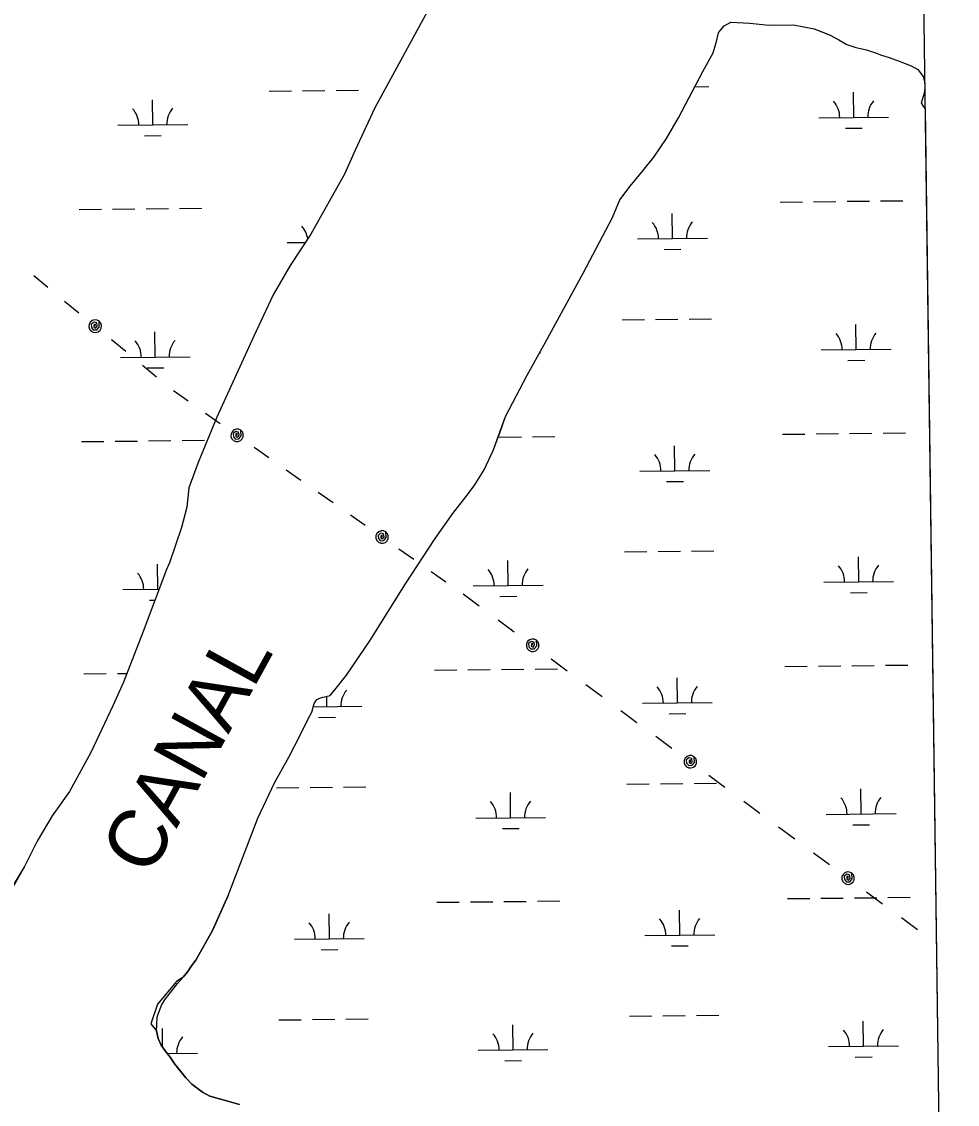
# Model space of a CAD drawing. Extents: x 3734862 to 3772949, y 391520 to 417239.
# Drawn here: x 3769504 to 3770844, y 399269 to 400820 of the extents above; entities that cross this region are included whole.
import ezdxf

# ---------------------------------------------------------------- set-up
doc = ezdxf.new("R2010")
doc.units = 0
for name, color, linetype in [('V-GRID-FRAM', 7, 'Continuous'), ('V-RIVR-IDEN', 7, 'Continuous'), ('V-TOPO-SHOR', 7, 'Continuous'), ('V-UTIL-LINE', 7, 'Continuous'), ('V-WETL-SWMP', 7, 'Continuous')]:
    doc.layers.add(name, color=color, linetype=linetype)

msp = doc.modelspace()

# ---------------------------------------------------------------- linework, layer by layer
at = {"layer": 'V-GRID-FRAM'}
msp.add_lwpolyline([(3738832.3, 415033.8), (3770599.2, 415447.4), (3770843.8, 397266.6), (3739061.1, 396852.8), (3738832.3, 415033.8)], dxfattribs=at)
at = {"layer": 'V-TOPO-SHOR'}
for p, q in [((3769725.6, 399444.6), (3769698.5, 399412.3)), ((3769698.5, 399412.3), (3769688.7, 399384))]:
    msp.add_line(p, q, dxfattribs=at)
for points in [[(3770096, 400855.5), (3770009.8, 400696.7), (3769981.4, 400635.8), (3769966.3, 400601.7), (3769917.9, 400515.4), (3769888.6, 400470.9), (3769864, 400428.4), (3769836.3, 400369.6), (3769783.6, 400253.4), (3769756.6, 400188.5), (3769743.5, 400152.3), (3769740.5, 400124.4), (3769732.8, 400095.1), (3769715.8, 400044.6), (3769711.2, 400035), (3769677.7, 399946.2), (3769649.5, 399873.8), (3769634.4, 399839.7), (3769602.7, 399772.7), (3769572.2, 399717.2), (3769547.5, 399682.2), (3769526.3, 399645.9), (3769507.8, 399609.7), (3769479.7, 399559.2)], [(3769799.4, 399568.1), (3769842, 399678.7), (3769865.8, 399729.3), (3769886.4, 399766.3), (3769903.6, 399799.8), (3769914.1, 399821), (3769919.4, 399830.6), (3769922.7, 399842.9), (3769926.7, 399849), (3769933.4, 399851.8), (3769945.6, 399854.7), (3769954.3, 399865), (3769969, 399883.6), (3770002.3, 399932.9), (3770053.5, 400014.5), (3770096.1, 400079.6), (3770121.4, 400115.3), (3770140.1, 400139.3), (3770152.1, 400155.1), (3770166, 400177.7), (3770179.2, 400205.7), (3770188.4, 400231), (3770196.9, 400254.2), (3770228, 400313.7), (3770253.9, 400361), (3770308.2, 400459.5), (3770349.9, 400539.6), (3770360.5, 400564.9), (3770375.1, 400584.1), (3770393.2, 400606.1), (3770409.2, 400626), (3770427.2, 400652.7), (3770444.4, 400682.2), (3770460.3, 400712.3), (3770479.5, 400748.6), (3770494.1, 400775.3), (3770498.7, 400791.6), (3770501.9, 400803.9), (3770504.5, 400808), (3770509.9, 400814.2), (3770519.3, 400819.1), (3770546.5, 400818.1), (3770573.7, 400815.1), (3770609.1, 400815.6), (3770639, 400809.9), (3770648.6, 400805.9), (3770661.6, 400800.7), (3770673.9, 400794), (3770685.5, 400787.4), (3770698.5, 400782.8), (3770713.5, 400779.6), (3770725.1, 400775.7), (3770735.3, 400771.8), (3770746.2, 400768.5), (3770760.6, 400763.3), (3770777.7, 400756.7), (3770787.2, 400751.4), (3770794.9, 400741.3), (3770797.2, 400732.1)], [(3770797.3, 400725.1), (3770796.5, 400717.6), (3770796.5, 400716.9), (3770792, 400703.9), (3770795.4, 400697.9), (3770797.7, 400695.1)], [(3769799.4, 399568.1), (3769777.2, 399517.9), (3769753.5, 399475.4), (3769747.3, 399467.4), (3769741.9, 399459), (3769735.3, 399451), (3769725.6, 399444.6)], [(3769688.7, 399384), (3769697.2, 399374), (3769699.4, 399363.2), (3769703.6, 399353.6), (3769709.3, 399345.5), (3769716.6, 399336.2), (3769723.4, 399326.2), (3769731.8, 399315.8), (3769739, 399306.9), (3769747.8, 399297.6), (3769762.7, 399286), (3769773.4, 399280.6), (3769788.4, 399276.3), (3769802.6, 399272.3), (3769816, 399268.8)]]:
    msp.add_lwpolyline(points, dxfattribs=at)
at = {"layer": 'V-UTIL-LINE'}
for points in [[(3769521.1, 400456.2), (3769541.5, 400439.4)], [(3769565.4, 400419.7), (3769585.8, 400402.9)], [(3769609.1, 400383.7), (3769609.4, 400386.6), (3769607.4, 400385.4), (3769607.2, 400382.7), (3769609.7, 400381.1), (3769611.9, 400383.6), (3769611.6, 400388.3), (3769607.5, 400389.4), (3769603.5, 400386.6), (3769603.7, 400382), (3769606.5, 400378.5), (3769611.3, 400378.5), (3769615, 400382.5), (3769614.9, 400390.7), (3769611.8, 400392.3), (3769608.3, 400392.7), (3769604.9, 400391.7), (3769602.2, 400389.4), (3769600.5, 400386.3), (3769600.2, 400382.8), (3769601.2, 400379.5), (3769603.4, 400376.8), (3769606.5, 400375.1), (3769610, 400374.8), (3769613.4, 400375.8), (3769616.1, 400378), (3769617.8, 400381.1), (3769618.1, 400384.6), (3769617.1, 400387.9), (3769614.9, 400390.7)], [(3769632.5, 400364.5), (3769652.9, 400347.7)], [(3769676.8, 400328), (3769697.2, 400311.2)], [(3769721.1, 400291.5), (3769742.2, 400276.7)], [(3769767.1, 400259.2), (3769788.2, 400244.4)], [(3769812.5, 400227.4), (3769812.5, 400230.2), (3769810.6, 400228.9), (3769810.6, 400226.2), (3769813.2, 400224.8), (3769815.3, 400227.4), (3769814.6, 400232.1), (3769810.4, 400232.9), (3769806.6, 400229.8), (3769807.2, 400225.2), (3769810.2, 400221.9), (3769815, 400222.3), (3769818.4, 400226.6), (3769817.6, 400234.7), (3769814.4, 400236.1), (3769810.9, 400236.2), (3769807.6, 400235), (3769805.1, 400232.5), (3769803.7, 400229.3), (3769803.6, 400225.8), (3769804.9, 400222.5), (3769807.3, 400220), (3769810.5, 400218.6), (3769814, 400218.5), (3769817.3, 400219.8), (3769819.8, 400222.2), (3769821.2, 400225.4), (3769821.3, 400228.9), (3769820.1, 400232.2), (3769817.6, 400234.7)], [(3769836.7, 400210.3), (3769857.8, 400195.5)], [(3769882.7, 400178), (3769903.8, 400163.2)], [(3769928.7, 400145.8), (3769949.8, 400130.9)], [(3769974.6, 400113.5), (3769995.8, 400098.6)], [(3770020, 400081.6), (3770020, 400084.5), (3770018.1, 400083.2), (3770018.2, 400080.4), (3770020.7, 400079), (3770022.8, 400081.7), (3770022.1, 400086.3), (3770017.9, 400087.1), (3770014.2, 400084), (3770014.7, 400079.5), (3770017.7, 400076.2), (3770022.6, 400076.5), (3770026, 400080.8), (3770025.2, 400089), (3770022, 400090.4), (3770018.5, 400090.5), (3770015.2, 400089.2), (3770012.6, 400086.8), (3770011.2, 400083.6), (3770011.1, 400080), (3770012.4, 400076.8), (3770014.8, 400074.2), (3770018, 400072.8), (3770021.6, 400072.7), (3770024.8, 400074), (3770027.4, 400076.4), (3770028.8, 400079.6), (3770028.9, 400083.1), (3770027.6, 400086.4), (3770025.2, 400089)], [(3770044.2, 400064.6), (3770065.4, 400049.7)], [(3770090.2, 400032.3), (3770111.4, 400017.4)], [(3770136.2, 400000), (3770159.2, 399983)], [(3770186.2, 399963), (3770209.2, 399946)], [(3770235.6, 399926.5), (3770235.7, 399929.4), (3770233.8, 399928.1), (3770233.7, 399925.4), (3770236.3, 399923.9), (3770238.4, 399926.6), (3770237.8, 399931.2), (3770233.7, 399932.1), (3770229.8, 399929.1), (3770230.3, 399924.5), (3770233.2, 399921.2), (3770238, 399921.4), (3770241.6, 399925.7), (3770241, 399933.8), (3770237.8, 399935.3), (3770234.3, 399935.4), (3770231, 399934.3), (3770228.4, 399931.9), (3770226.9, 399928.7), (3770226.7, 399925.2), (3770227.9, 399921.9), (3770230.3, 399919.3), (3770233.4, 399917.8), (3770236.9, 399917.6), (3770240.3, 399918.8), (3770242.9, 399921.2), (3770244.3, 399924.4), (3770244.5, 399927.9), (3770243.3, 399931.2), (3770241, 399933.8)], [(3770262, 399907.1), (3770285, 399890.1)], [(3770312, 399870.1), (3770335, 399853.1)], [(3770362.1, 399833.1), (3770385, 399816.1)], [(3770412.1, 399796.1), (3770435.1, 399779.2)], [(3770461.5, 399759.7), (3770461.5, 399762.6), (3770459.6, 399761.3), (3770459.6, 399758.5), (3770462.1, 399757.1), (3770464.3, 399759.7), (3770463.7, 399764.3), (3770459.5, 399765.2), (3770455.7, 399762.2), (3770456.1, 399757.7), (3770459.1, 399754.3), (3770463.9, 399754.6), (3770467.4, 399758.8), (3770466.8, 399766.9), (3770463.6, 399768.4), (3770460.1, 399768.6), (3770456.8, 399767.4), (3770454.2, 399765), (3770452.7, 399761.8), (3770452.6, 399758.3), (3770453.7, 399755), (3770456.1, 399752.4), (3770459.3, 399750.9), (3770462.8, 399750.8), (3770466.1, 399752), (3770468.7, 399754.3), (3770470.2, 399757.5), (3770470.4, 399761), (3770469.2, 399764.3), (3770466.8, 399766.9)], [(3770487.8, 399740.2), (3770510.8, 399723.2)], [(3770537.9, 399703.2), (3770560.9, 399686.2)], [(3770587.9, 399666.2), (3770610.9, 399649.3)], [(3770637.9, 399629.3), (3770660.9, 399612.3)], [(3770687.3, 399592.8), (3770687.4, 399595.7), (3770685.4, 399594.4), (3770685.4, 399591.7), (3770688, 399590.2), (3770690.1, 399592.8), (3770689.5, 399597.5), (3770685.4, 399598.4), (3770681.5, 399595.4), (3770682, 399590.8), (3770684.9, 399587.4), (3770689.7, 399587.7), (3770693.3, 399591.9), (3770692.7, 399600), (3770689.5, 399601.5), (3770686, 399601.7), (3770682.7, 399600.5), (3770680.1, 399598.2), (3770678.6, 399595), (3770678.4, 399591.5), (3770679.6, 399588.2), (3770682, 399585.6), (3770685.1, 399584.1), (3770688.6, 399583.9), (3770691.9, 399585.1), (3770694.5, 399587.5), (3770696, 399590.6), (3770696.2, 399594.1), (3770695, 399597.4), (3770692.7, 399600)], [(3770713.7, 399573.3), (3770736.7, 399556.3)], [(3770763.7, 399536.4), (3770786.7, 399519.4)]]:
    msp.add_lwpolyline(points, dxfattribs=at)
at = {"layer": 'V-WETL-SWMP'}
for p, q in [((3770504.5, 400808), (3770509.9, 400814.2)), ((3770509.9, 400814.2), (3770519.3, 400819.1)), ((3770519.3, 400819.1), (3770546.5, 400818.1)), ((3770546.5, 400818.1), (3770573.7, 400815.1)), ((3770573.7, 400815.1), (3770609.1, 400815.6)), ((3770609.1, 400815.6), (3770639, 400809.9)), ((3770498.7, 400791.6), (3770501.9, 400803.9)), ((3770501.9, 400803.9), (3770504.5, 400808)), ((3770639, 400809.9), (3770661.6, 400800.7)), ((3770661.6, 400800.7), (3770673.9, 400794)), ((3770494.1, 400775.3), (3770498.7, 400791.6)), ((3770673.9, 400794), (3770685.5, 400787.4)), ((3770685.5, 400787.4), (3770698.5, 400782.8)), ((3770698.5, 400782.8), (3770713.5, 400779.6)), ((3770479.5, 400748.6), (3770494.1, 400775.3)), ((3770713.5, 400779.6), (3770725.1, 400775.7)), ((3770725.1, 400775.7), (3770735.3, 400771.8)), ((3770735.3, 400771.8), (3770746.2, 400768.5)), ((3770746.2, 400768.5), (3770760.6, 400763.3)), ((3770760.6, 400763.3), (3770777.7, 400756.7)), ((3770777.7, 400756.7), (3770787.2, 400751.4)), ((3770787.2, 400751.4), (3770794.9, 400741.3)), ((3770444.4, 400682.2), (3770479.5, 400748.6)), ((3770794.9, 400741.3), (3770797.2, 400732.1)), ((3769858.2, 400720.3), (3769890.2, 400720.7)), ((3769906.2, 400720.9), (3769938.2, 400721.2)), ((3769954.2, 400721.4), (3769986.2, 400721.7)), ((3770468, 400726.8), (3770488.1, 400727)), ((3770797.3, 400725.1), (3770796.5, 400717.6)), ((3770797.2, 400732.1), (3770797.3, 400725.1)), ((3769691.7, 400672.2), (3769691.3, 400708.2)), ((3770695.4, 400682.8), (3770695.1, 400718.8)), ((3770796.5, 400716.9), (3770792, 400703.9)), ((3770796.5, 400717.6), (3770796.5, 400716.9)), ((3770792, 400703.9), (3770795.4, 400697.9)), ((3770795.4, 400697.9), (3770797.7, 400695.1)), ((3770797.7, 400695.1), (3770823.2, 398800.6)), ((3770427.2, 400652.7), (3770444.4, 400682.2)), ((3770645.4, 400682.2), (3770745.4, 400683.3)), ((3769641.7, 400671.6), (3769741.7, 400672.7)), ((3770683.6, 400667.2), (3770707.6, 400667.5)), ((3769679.8, 400656.6), (3769703.8, 400656.9)), ((3770409.2, 400626), (3770427.2, 400652.7)), ((3770393.2, 400606.1), (3770409.2, 400626)), ((3770375.1, 400584.1), (3770393.2, 400606.1)), ((3770360.5, 400564.9), (3770375.1, 400584.1)), ((3770349.9, 400539.6), (3770360.5, 400564.9)), ((3769586.1, 400551), (3769618.1, 400551.3)), ((3769634.1, 400551.5), (3769666.1, 400551.8)), ((3769682.1, 400552), (3769714.1, 400552.3)), ((3769730.1, 400552.5), (3769762.1, 400552.8)), ((3770589.9, 400561.6), (3770621.9, 400561.9)), ((3770637.9, 400562.1), (3770669.9, 400562.4)), ((3770685.9, 400562.6), (3770717.9, 400562.9)), ((3770733.9, 400563.1), (3770765.9, 400563.4)), ((3770308.2, 400459.5), (3770349.9, 400539.6)), ((3770435.8, 400509.2), (3770435.4, 400545.2)), ((3769884, 400503.4), (3769910.2, 400503.6)), ((3770385.8, 400508.7), (3770485.8, 400509.7)), ((3770424, 400493.6), (3770448, 400493.9)), ((3770253.9, 400361), (3770308.2, 400459.5)), ((3770459.6, 400394), (3770491.6, 400394.3)), ((3770363.6, 400393), (3770395.6, 400393.3)), ((3770411.6, 400393.5), (3770443.6, 400393.8)), ((3770699, 400350.1), (3770698.6, 400386.1)), ((3769695.2, 400339.5), (3769694.8, 400375.5)), ((3770228, 400313.7), (3770253.9, 400361)), ((3770649, 400349.6), (3770749, 400350.6)), ((3769645.2, 400339), (3769745.2, 400340)), ((3770245.3, 400345.3), (3770247.1, 400345.3)), ((3770687.1, 400334.5), (3770711.1, 400334.8)), ((3769683.4, 400323.9), (3769707.4, 400324.2)), ((3770196.9, 400254.2), (3770228, 400313.7)), ((3770179.2, 400205.7), (3770196.9, 400254.2)), ((3770187.5, 400224.6), (3770219.5, 400225)), ((3770235.5, 400225.1), (3770267.5, 400225.5)), ((3770593.4, 400228.9), (3770625.4, 400229.2)), ((3770641.4, 400229.4), (3770673.4, 400229.8)), ((3770689.4, 400229.9), (3770721.4, 400230.3)), ((3770737.4, 400230.4), (3770769.4, 400230.8)), ((3769589.6, 400218.3), (3769621.6, 400218.6)), ((3769637.6, 400218.8), (3769669.6, 400219.2)), ((3769685.6, 400219.3), (3769717.6, 400219.7)), ((3769733.6, 400219.8), (3769765.6, 400220.2)), ((3770439.3, 400176.5), (3770439, 400212.5)), ((3770166, 400177.7), (3770179.2, 400205.7)), ((3770152.1, 400155.1), (3770166, 400177.7)), ((3770389.3, 400176), (3770489.3, 400177.1)), ((3770140.1, 400139.3), (3770152.1, 400155.1)), ((3770427.5, 400161), (3770451.5, 400161.2)), ((3770121.4, 400115.3), (3770140.1, 400139.3)), ((3770096.1, 400079.6), (3770121.4, 400115.3)), ((3770053.5, 400014.5), (3770096.1, 400079.6)), ((3770367.2, 400060.3), (3770399.2, 400060.7)), ((3770415.2, 400060.8), (3770447.2, 400061.2)), ((3770463.2, 400061.4), (3770495.2, 400061.7)), ((3770702.5, 400017.4), (3770702.1, 400053.4)), ((3769698.7, 400006.8), (3769698.3, 400042.8)), ((3770200.6, 400012.1), (3770200.2, 400048.1)), ((3769648.7, 400006.3), (3769700.6, 400006.9)), ((3770002.3, 399932.9), (3770053.5, 400014.5)), ((3770150.6, 400011.6), (3770250.6, 400012.7)), ((3770652.5, 400016.9), (3770752.5, 400018)), ((3769686.9, 399991.3), (3769694.7, 399991.4)), ((3770188.8, 399996.6), (3770212.8, 399996.8)), ((3770690.6, 400001.9), (3770714.6, 400002.1)), ((3769969, 399883.6), (3770002.3, 399932.9)), ((3770740.9, 399897.8), (3770772.9, 399898.1)), ((3769593.1, 399885.7), (3769625.1, 399886)), ((3769641.1, 399886.2), (3769654.4, 399886.3)), ((3769954.3, 399865), (3769969, 399883.6)), ((3770095, 399891), (3770127, 399891.3)), ((3770143, 399891.5), (3770175, 399891.8)), ((3770191, 399892), (3770223, 399892.3)), ((3770239, 399892.5), (3770271, 399892.8)), ((3770596.9, 399896.3), (3770628.9, 399896.6)), ((3770644.9, 399896.8), (3770676.9, 399897.1)), ((3770692.9, 399897.3), (3770724.9, 399897.6)), ((3770442.9, 399843.9), (3770442.5, 399879.9)), ((3769926.7, 399849), (3769933.4, 399851.8)), ((3769933.4, 399851.8), (3769945.6, 399854.7)), ((3769941, 399838.6), (3769940.8, 399853.6)), ((3769945.6, 399854.7), (3769954.3, 399865)), ((3769919.4, 399830.6), (3769922.7, 399842.9)), ((3769921.5, 399838.4), (3769991, 399839.1)), ((3769922.7, 399842.9), (3769926.7, 399849)), ((3770392.9, 399843.4), (3770492.9, 399844.4)), ((3769903.6, 399799.8), (3769914.1, 399821)), ((3769914.1, 399821), (3769919.4, 399830.6)), ((3769929.1, 399823), (3769953.1, 399823.3)), ((3770431, 399828.3), (3770455, 399828.6)), ((3769886.4, 399766.3), (3769903.6, 399799.8)), ((3769865.8, 399729.3), (3769886.4, 399766.3)), ((3769842, 399678.7), (3769865.8, 399729.3)), ((3770370.7, 399727.7), (3770402.7, 399728)), ((3770418.7, 399728.2), (3770450.7, 399728.5)), ((3770466.7, 399728.7), (3770498.7, 399729)), ((3769868.8, 399722.4), (3769900.8, 399722.7)), ((3769916.8, 399722.9), (3769948.8, 399723.2)), ((3769964.8, 399723.4), (3769996.8, 399723.7)), ((3770204.1, 399679.5), (3770203.7, 399715.5)), ((3770706, 399684.8), (3770705.6, 399720.8)), ((3770656, 399684.3), (3770756, 399685.3)), ((3769799.4, 399568.1), (3769842, 399678.7)), ((3770154.1, 399679), (3770254.1, 399680)), ((3770694.2, 399669.2), (3770718.1, 399669.5)), ((3770192.3, 399663.9), (3770216.3, 399664.2)), ((3769777.2, 399517.9), (3769799.4, 399568.1)), ((3770098.5, 399558.3), (3770130.5, 399558.6)), ((3770146.5, 399558.8), (3770178.5, 399559.1)), ((3770194.5, 399559.3), (3770226.5, 399559.6)), ((3770242.5, 399559.8), (3770274.5, 399560.2)), ((3770600.4, 399563.6), (3770632.4, 399563.9)), ((3770648.4, 399564.1), (3770680.4, 399564.4)), ((3770696.4, 399564.6), (3770728.4, 399564.9)), ((3770744.4, 399565.1), (3770776.4, 399565.5)), ((3769944.5, 399505.9), (3769944.1, 399541.9)), ((3770446.4, 399511.2), (3770446, 399547.2)), ((3769753.5, 399475.4), (3769777.2, 399517.9)), ((3770396.4, 399510.7), (3770496.4, 399511.8)), ((3769894.5, 399505.4), (3769994.5, 399506.5)), ((3770434.5, 399495.7), (3770458.5, 399495.9)), ((3769932.7, 399490.4), (3769956.7, 399490.6)), ((3769741.9, 399459), (3769747.3, 399467.4)), ((3769747.3, 399467.4), (3769753.5, 399475.4)), ((3769727.2, 399441.8), (3769735.3, 399451)), ((3769735.3, 399451), (3769741.9, 399459)), ((3769709.8, 399420), (3769720.6, 399433.4)), ((3769720.6, 399433.4), (3769727.2, 399441.8)), ((3769704.7, 399412), (3769709.8, 399420)), ((3769699.3, 399398.2), (3769702, 399405.5)), ((3769702, 399405.5), (3769704.7, 399412)), ((3769697.3, 399383.2), (3769698.1, 399393.6)), ((3769698.1, 399393.6), (3769699.3, 399398.2)), ((3769872.3, 399389.7), (3769904.3, 399390.1)), ((3769920.3, 399390.2), (3769952.3, 399390.6)), ((3769968.3, 399390.7), (3770000.3, 399391.1)), ((3770374.2, 399395), (3770406.2, 399395.4)), ((3770422.2, 399395.5), (3770454.2, 399395.9)), ((3770470.2, 399396), (3770502.2, 399396.4)), ((3770709.5, 399352.1), (3770709.1, 399388.1)), ((3769697.2, 399374), (3769697.3, 399383.2)), ((3769699.4, 399363.2), (3769697.2, 399374)), ((3769705.6, 399350.7), (3769705.4, 399377.5)), ((3770207.6, 399346.8), (3770207.2, 399382.8)), ((3769703.6, 399353.6), (3769699.4, 399363.2)), ((3769709.3, 399345.5), (3769703.6, 399353.6)), ((3769716.6, 399336.2), (3769709.3, 399345.5)), ((3769712.4, 399341.6), (3769755.7, 399342.1)), ((3770157.6, 399346.3), (3770257.6, 399347.4)), ((3770659.5, 399351.6), (3770759.5, 399352.7)), ((3769723.4, 399326.2), (3769716.6, 399336.2)), ((3769739, 399306.9), (3769723.4, 399326.2)), ((3770195.8, 399331.3), (3770219.8, 399331.5)), ((3770697.7, 399336.6), (3770721.7, 399336.8)), ((3769747.8, 399297.6), (3769739, 399306.9)), ((3769762.7, 399286), (3769747.8, 399297.6)), ((3769773.4, 399280.6), (3769762.7, 399286)), ((3769788.4, 399276.3), (3769773.4, 399280.6)), ((3769802.6, 399272.3), (3769788.4, 399276.3)), ((3769816, 399268.8), (3769802.6, 399272.3))]:
    msp.add_line(p, q, dxfattribs=at)
msp.add_lwpolyline([(3770096, 400855.5), (3770009.8, 400696.7), (3769981.4, 400635.8), (3769966.3, 400601.7), (3769917.9, 400515.4), (3769888.6, 400470.9), (3769864, 400428.4), (3769836.3, 400369.6), (3769783.6, 400253.4), (3769756.6, 400188.5), (3769743.5, 400152.3), (3769740.5, 400124.4), (3769732.8, 400095.1), (3769715.8, 400044.6), (3769711.2, 400035), (3769677.7, 399946.2), (3769649.5, 399873.8), (3769634.4, 399839.7), (3769602.7, 399772.7), (3769572.2, 399717.2), (3769547.5, 399682.2), (3769526.3, 399645.9), (3769507.8, 399609.7), (3769486.5, 399574.1)], dxfattribs=at)
for centre, start, end in [((3770640.2, 400682.7), 359.8334, 41.377), ((3770750.7, 400683.8), 139.8334, 181.377), ((3769636.4, 400672), 359.8334, 41.377), ((3769746.9, 400673.2), 139.8334, 181.377), ((3769878.7, 400503.8), 8.2839, 41.377), ((3770380.6, 400509.1), 359.8334, 41.377), ((3770491.1, 400510.3), 139.8334, 181.377), ((3769750.4, 400340.6), 139.8334, 181.377), ((3770643.7, 400350), 359.8334, 41.377), ((3770754.2, 400351.2), 139.8334, 181.377), ((3769640, 400339.4), 359.8334, 41.377), ((3770384.1, 400176.4), 359.8334, 41.377), ((3770494.6, 400177.6), 139.8334, 181.377), ((3770647.2, 400017.3), 359.8334, 41.377), ((3770757.7, 400018.5), 139.8334, 181.377), ((3769643.5, 400006.7), 359.8334, 41.377), ((3770145.3, 400012), 359.8334, 41.377), ((3770255.8, 400013.2), 139.8334, 181.377), ((3770387.6, 399843.8), 359.8334, 41.377), ((3770498.1, 399844.9), 139.8334, 181.377), ((3769996.2, 399839.6), 139.8334, 181.377), ((3770148.9, 399679.4), 359.8334, 41.377), ((3770259.3, 399680.5), 139.8334, 181.377), ((3770650.7, 399684.7), 359.8334, 41.377), ((3770761.2, 399685.8), 139.8334, 181.377), ((3769889.2, 399505.8), 359.8334, 41.377), ((3769999.7, 399507), 139.8334, 181.377), ((3770391.1, 399511.1), 359.8334, 41.377), ((3770501.6, 399512.3), 139.8334, 181.377), ((3770262.9, 399347.9), 139.8334, 181.377), ((3770654.3, 399352), 359.8334, 41.377), ((3770764.7, 399353.2), 139.8334, 181.377), ((3769761, 399342.6), 139.8334, 181.377), ((3770152.4, 399346.7), 359.8334, 41.377)]:
    msp.add_arc(centre, 35.2, start, end, dxfattribs=at)

# ---------------------------------------------------------------- texts
at = {"layer": 'V-RIVR-IDEN'}
msp.add_text('CANAL', height=83, rotation=61.1731, dxfattribs=at).set_placement((3769686.9, 399593))

doc.saveas('drawing.dxf')
